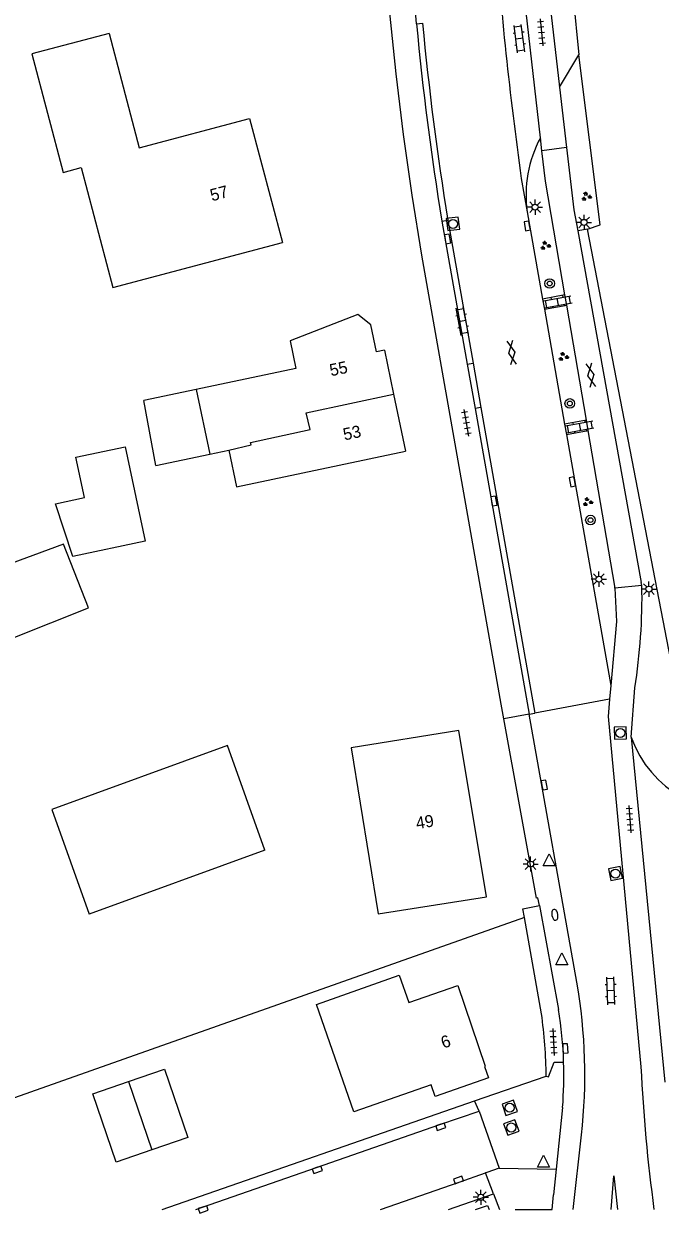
# Model space of a CAD drawing. Extents: x 136000 to 141000, y 400494 to 402006.
# Drawn here: x 137913.3 to 137966.1, y 400499.7 to 400598.3 of the extents above; entities that cross this region are included whole.
import ezdxf

# ---------------------------------------------------------------- set-up
doc = ezdxf.new("R2010")
doc.units = 0
for name, color, linetype in [('gg-afsc-erfafscheiding', 7, 'Continuous'), ('gg-afsc-hekwerk', 7, 'Continuous'), ('gg-anno-huisnummerreeks BGT', 7, 'Continuous'), ('gg-bbg-bijgebouw', 7, 'Continuous'), ('gg-bbg-gedigitaliseerde bebouwing', 7, 'Continuous'), ('gg-bbg-gedigitaliseerde bijgebouw', 7, 'Continuous'), ('gg-bbg-hoofdgebouw', 7, 'Continuous'), ('gg-bbg-tussenscheiding', 7, 'Continuous'), ('gg-knt-verharding', 7, 'Continuous'), ('gg-knt-verharding nz', 7, 'Continuous'), ('gt-grn-groengrens', 7, 'Continuous'), ('gt-grn-vlakafsluiter', 7, 'Continuous'), ('gt-grn-weggrens', 7, 'Continuous'), ('gt-symb-boom', 7, 'Continuous'), ('gt-symb-brandkraan', 7, 'Continuous'), ('gt-symb-gesloten verharding', 7, 'Continuous'), ('gt-symb-groenvak', 7, 'Continuous'), ('gt-symb-klinker verharding', 7, 'Continuous'), ('gt-symb-kolk', 7, 'Continuous'), ('gt-symb-lichtmast', 7, 'Continuous'), ('gt-symb-rioolschacht', 7, 'Continuous'), ('gt-symb-tegel verharding', 7, 'Continuous'), ('gt-symb-waterafsluiter', 7, 'Continuous')]:
    doc.layers.add(name, color=color, linetype=linetype)

# ---------------------------------------------------------------- blocks, each defined once
blk = doc.blocks.new('gt0-KL1')
at = {"layer": 'gt-symb-klinker verharding'}
for p, q in [((-1.15, 0.3), (1.15, 0.3)), ((-1, -0.3), (-1, 0.3)), ((-0.5, 0.3), (-0.5, 0.45)), ((0, -0.3), (0, 0.3)), ((0.5, 0.3), (0.5, 0.45)), ((1, -0.3), (1, 0.3)), ((-1.15, -0.3), (1.15, -0.3)), ((-0.5, -0.45), (-0.5, -0.3)), ((0.5, -0.45), (0.5, -0.3))]:
    blk.add_line(p, q, dxfattribs=at)
blk = doc.blocks.new('gt0-TEG1')
at = {"layer": 'gt-symb-tegel verharding'}
for p, q in [((-1.125, 0), (1.125, 0)), ((-0.9, -0.25), (-0.9, 0.25)), ((-0.45, -0.25), (-0.45, 0.25)), ((0, -0.25), (0, 0.25)), ((0.45, -0.25), (0.45, 0.25)), ((0.9, -0.25), (0.9, 0.25))]:
    blk.add_line(p, q, dxfattribs=at)
blk = doc.blocks.new('gt0-BOOM')
at = {"layer": 'gt-symb-boom'}
for radius in [0.4, 0.2]:
    blk.add_circle((0, 0), radius, dxfattribs=at)
blk = doc.blocks.new('gt0-GRVAK')
at = {"layer": 'gt-symb-groenvak'}
for p, q in [((-0.11, 0.189), (-0.228, 0.24)), ((-0.182, 0.153), (0.088, 0.153)), ((-0.091, 0.211), (-0.156, 0.322)), ((-0.047, 0.214), (-0.047, 0.393)), ((-0.004, 0.211), (0.061, 0.322)), ((0.015, 0.189), (0.133, 0.24)), ((0.262, -0.052), (0.197, 0.059)), ((0.305, -0.049), (0.305, 0.13)), ((0.349, -0.052), (0.414, 0.059)), ((-0.245, -0.228), (-0.363, -0.177)), ((-0.318, -0.264), (-0.047, -0.264)), ((-0.226, -0.206), (-0.291, -0.095)), ((-0.183, -0.203), (-0.183, -0.024)), ((-0.139, -0.206), (-0.074, -0.095)), ((-0.12, -0.228), (-0.002, -0.177)), ((0.243, -0.074), (0.125, -0.023)), ((0.17, -0.11), (0.441, -0.11)), ((0.368, -0.074), (0.486, -0.023))]:
    blk.add_line(p, q, dxfattribs=at)
blk = doc.blocks.new('gt0-KOLK')
at = {"layer": 'gt-symb-kolk'}
blk.add_lwpolyline([(0, 0), (0.375, 0), (0.375, 0.4), (-0.375, 0.4), (-0.375, 0), (0, 0)], dxfattribs=at)
blk = doc.blocks.new('gt0-LMAST')
at = {"layer": 'gt-symb-lichtmast'}
for p, q in [((-0.182, 0.173), (-0.447, 0.438)), ((-0.005, 0.246), (-0.005, 0.621)), ((0.172, 0.173), (0.437, 0.438)), ((-0.255, -0.004), (-0.63, -0.004)), ((-0.182, -0.181), (-0.447, -0.446)), ((-0.005, -0.254), (-0.005, -0.629)), ((0.437, -0.446), (0.172, -0.181)), ((0.245, -0.004), (0.62, -0.004))]:
    blk.add_line(p, q, dxfattribs=at)
blk.add_circle((-0.005, -0.004), 0.25, dxfattribs=at)
blk = doc.blocks.new('gt0-GESVH1')
at = {"layer": 'gt-symb-gesloten verharding'}
for p, q in [((-0.992, -0.261), (0.008, 0.239)), ((0.008, -0.261), (-0.992, 0.239)), ((0.008, 0.239), (1.008, -0.261)), ((1.008, 0.239), (0.008, -0.261))]:
    blk.add_line(p, q, dxfattribs=at)
blk = doc.blocks.new('gt0-RS')
at = {"layer": 'gt-symb-rioolschacht'}
blk.add_lwpolyline([(-0.5, -0.5), (0.5, -0.5), (0.5, 0.5), (-0.5, 0.5)], close=True, dxfattribs=at)
blk.add_circle((0, 0), 0.375, dxfattribs=at)
blk = doc.blocks.new('gt0-WAFSL')
at = {"layer": 'gt-symb-waterafsluiter'}
for p, q in [((-0.5, -0.333), (0, 0.667)), ((0, 0.667), (0.5, -0.333)), ((0.5, -0.333), (-0.5, -0.333))]:
    blk.add_line(p, q, dxfattribs=at)
blk = doc.blocks.new('gt0-BR')
at = {"layer": 'gt-symb-brandkraan'}
for centre, radius, start, end in [((-0.244, 0), 0.206, 107.56694, 252.43307), ((0.599, -2.664), 3, 106.89205, 107.56694), ((0, -0.691), 0.938, 73.10799, 106.89205), ((-0.599, -2.664), 3, 72.43309, 73.10799), ((0.244, 0), 0.206, 287.56695, 72.43309), ((0.599, 2.664), 3, 252.43307, 253.10797), ((0, 0.691), 0.938, 253.10797, 286.89206), ((-0.599, 2.664), 3, 286.89206, 287.56695)]:
    blk.add_arc(centre, radius, start, end, dxfattribs=at)

msp = doc.modelspace()

# ---------------------------------------------------------------- linework, layer by layer
at = {"layer": 'gg-afsc-erfafscheiding'}
for p, q in [((137958.199, 400607.146), (137959.332, 400595.725)), ((137954.822, 400524.219), (137888.451, 400500.743))]:
    msp.add_line(p, q, dxfattribs=at)
at = {"layer": 'gg-afsc-hekwerk'}
for points in [[(137960.064, 400581.277), (137961.101, 400581.627), (137959.332, 400595.725)], [(137984.525, 400540.311), (137968.565, 400537.24), (137960.064, 400581.277)]]:
    msp.add_lwpolyline(points, dxfattribs=at)
at = {"layer": 'gg-bbg-bijgebouw'}
for p, q in [((137933.305, 400529.801), (137918.721, 400524.489)), ((137926.909, 400505.977), (137923.936, 400504.955))]:
    msp.add_line(p, q, dxfattribs=at)
for points in [[(137921.993, 400510.61), (137924.964, 400511.632), (137926.909, 400505.977)], [(137923.936, 400504.955), (137920.963, 400503.932), (137919.021, 400509.588), (137921.993, 400510.61)]]:
    msp.add_lwpolyline(points, dxfattribs=at)
at = {"layer": 'gg-bbg-gedigitaliseerde bebouwing'}
for p, q in [((137935.877, 400569.71), (137927.592, 400567.982)), ((137928.743, 400562.62), (137930.311, 400562.949))]:
    msp.add_line(p, q, dxfattribs=at)
for points in [[(137920.39, 400597.49), (137913.978, 400595.804), (137916.562, 400585.978), (137918.069, 400586.385), (137920.705, 400576.438), (137934.75, 400580.16)], [(137930.311, 400562.949), (137930.95, 400559.907), (137944.97, 400562.86)], [(137949.4, 400539.7), (137940.445, 400538.265), (137942.698, 400524.518)]]:
    msp.add_lwpolyline(points, dxfattribs=at)
at = {"layer": 'gg-bbg-gedigitaliseerde bijgebouw'}
for p, q in [((137927.592, 400567.982), (137923.256, 400567.078)), ((137924.27, 400561.68), (137923.256, 400567.078)), ((137924.27, 400561.68), (137928.743, 400562.62))]:
    msp.add_line(p, q, dxfattribs=at)
for points in [[(137915.93, 400558.516), (137918.328, 400559.019), (137917.626, 400562.365), (137921.722, 400563.226), (137923.365, 400555.396), (137917.375, 400554.139), (137915.93, 400558.516)], [(137916.593, 400555.172), (137904.065, 400550.556), (137906.279, 400544.971), (137918.684, 400549.89), (137916.593, 400555.172)], [(137933.305, 400529.801), (137930.213, 400538.475), (137915.637, 400533.157), (137918.721, 400524.489)]]:
    msp.add_lwpolyline(points, dxfattribs=at)
at = {"layer": 'gg-bbg-hoofdgebouw'}
for p, q in [((137943.21, 400571.24), (137943.977, 400567.588)), ((137943.977, 400567.588), (137944.97, 400562.86))]:
    msp.add_line(p, q, dxfattribs=at)
for points in [[(137920.39, 400597.49), (137922.88, 400588.02), (137932.04, 400590.44), (137934.75, 400580.16)], [(137943.21, 400571.24), (137942.564, 400571.104), (137942.094, 400573.335), (137941.001, 400574.193), (137935.39, 400572.03), (137935.877, 400569.71)], [(137942.698, 400524.518), (137951.684, 400525.917), (137949.4, 400539.7)], [(137937.573, 400517.01), (137944.444, 400519.425), (137945.236, 400517.151), (137949.299, 400518.564), (137951.585, 400511.889), (137951.518, 400511.866), (137951.845, 400510.929), (137947.413, 400509.383), (137947.083, 400510.33), (137940.678, 400508.109), (137937.573, 400517.01)]]:
    msp.add_lwpolyline(points, dxfattribs=at)
at = {"layer": 'gg-bbg-tussenscheiding'}
for p, q in [((137927.592, 400567.982), (137928.743, 400562.62)), ((137921.993, 400510.61), (137923.936, 400504.955))]:
    msp.add_line(p, q, dxfattribs=at)
msp.add_lwpolyline([(137930.311, 400562.949), (137932.157, 400563.384), (137932.107, 400563.596), (137937.07, 400564.658), (137936.716, 400566.044), (137943.977, 400567.588)], dxfattribs=at)
at = {"layer": 'gg-knt-verharding'}
for p, q in [((137956.156, 400588.857), (137954.361, 400604.552)), ((137956.378, 400604.724), (137957.743, 400593.041)), ((137945.883, 400598.3), (137946.378, 400598.347)), ((137957.743, 400593.041), (137959.332, 400595.725)), ((137957.743, 400593.041), (137958.328, 400588.044)), ((137956.283, 400587.754), (137956.156, 400588.857)), ((137958.328, 400588.044), (137956.283, 400587.754)), ((137954.57, 400585.48), (137955.058, 400582.716)), ((137955.058, 400582.716), (137956.338, 400575.459)), ((137947.98, 400581.95), (137948.481, 400582.032)), ((137947.98, 400581.95), (137950.081, 400570.086)), ((137948.481, 400582.032), (137950.571, 400570.172)), ((137959.248, 400581.13), (137964.51, 400551.991)), ((137958.188, 400575.827), (137956.338, 400575.459)), ((137956.338, 400575.459), (137956.484, 400574.634)), ((137958.335, 400574.976), (137958.188, 400575.827)), ((137956.484, 400574.634), (137958.335, 400574.976)), ((137956.484, 400574.634), (137958.164, 400565.114)), ((137959.975, 400565.438), (137958.335, 400574.976)), ((137950.081, 400570.086), (137950.571, 400570.172)), ((137950.081, 400570.086), (137950.735, 400566.397)), ((137950.571, 400570.172), (137951.221, 400566.483)), ((137951.221, 400566.483), (137950.735, 400566.397)), ((137950.735, 400566.397), (137955.222, 400541.057)), ((137951.221, 400566.483), (137955.686, 400541.14)), ((137959.975, 400565.438), (137958.164, 400565.114)), ((137960.123, 400564.577), (137959.975, 400565.438)), ((137958.164, 400565.114), (137958.318, 400564.238)), ((137958.318, 400564.238), (137960.123, 400564.577)), ((137962.34, 400551.681), (137960.123, 400564.577)), ((137958.318, 400564.238), (137961.986, 400543.452)), ((137964.573, 400551.737), (137962.329, 400551.502)), ((137962.329, 400551.502), (137962.34, 400551.681)), ((137964.573, 400551.737), (137964.51, 400551.991)), ((137961.986, 400543.452), (137961.882, 400542.299)), ((137963.691, 400539.166), (137963.992, 400543.248)), ((137961.882, 400542.299), (137955.686, 400541.14)), ((137959.176, 400518.838), (137955.222, 400541.057)), ((137963.691, 400539.166), (137966.466, 400510.567)), ((137954.697, 400524.92), (137956.078, 400525.216)), ((137956.078, 400525.216), (137957.667, 400516.57)), ((137954.822, 400524.219), (137954.697, 400524.92)), ((137956.248, 400516.232), (137954.822, 400524.219)), ((137950.698, 400509), (137956.635, 400511.047)), ((137924.796, 400500), (137950.698, 400509)), ((137957.995, 400508.445), (137957.466, 400503.359)), ((137951.068, 400508.154), (137952.722, 400503.44)), ((137958.879, 400500), (137959.564, 400506.18)), ((137952.722, 400503.44), (137951.719, 400503.076)), ((137952.722, 400503.44), (137957.466, 400503.359)), ((137957.466, 400503.359), (137957.243, 400501.216)), ((137951.719, 400503.076), (137951.611, 400503.038)), ((137952.275, 400501.298), (137951.611, 400503.038)), ((137948.543, 400500), (137952.275, 400501.298)), ((137952.275, 400501.298), (137952.77, 400500)), ((137957.12, 400500.002), (137957.243, 400501.216)), ((137954.058, 400500), (137956.758, 400500.003)), ((137956.756, 400500), (137956.758, 400500.003)), ((137956.758, 400500.003), (137957.12, 400500.002)), ((137957.12, 400500), (137957.12, 400500.002))]:
    msp.add_line(p, q, dxfattribs=at)
for points in [[(137953.118, 400540.684), (137952.895, 400541.907), (137946.331, 400579.107), (137945.505, 400584.105), (137944.787, 400589.12), (137944.179, 400594.152), (137943.676, 400599.195), (137943.255, 400604.384), (137942.945, 400609.581), (137942.751, 400615.175), (137942.658, 400620.772), (137942.643, 400626.229), (137942.694, 400631.685), (137942.719, 400632.779)], [(137945.883, 400598.3), (137945.41, 400604.025), (137945.058, 400609.735), (137945.056, 400609.785)], [(137958.188, 400575.827), (137956.57, 400585.24), (137956.283, 400587.754)], [(137958.328, 400588.044), (137958.93, 400582.89), (137959.248, 400581.13)], [(137962.329, 400551.502), (137962.465, 400548.748), (137961.986, 400543.452)], [(137961.882, 400542.299), (137961.784, 400540.883), (137964.496, 400511.834)], [(137956.078, 400525.216), (137955.952, 400525.84), (137955.834, 400525.811), (137953.118, 400540.684)], [(137956.635, 400511.047), (137956.816, 400511.001), (137957.285, 400512.223), (137958.083, 400512.206)], [(137927.565, 400500), (137928.124, 400500.195), (137937.589, 400503.478), (137947.826, 400507.048), (137951.068, 400508.154)], [(137942.897, 400500), (137949.427, 400502.265), (137951.611, 400503.038)]]:
    msp.add_lwpolyline(points, dxfattribs=at)
for centre, radius, start, end in [((138246.395, 400626.641), 294.714, 183.96826, 188.02849), ((138179.597, 400619.966), 234.716, 185.29635, 189.32101), ((138188.724, 400621.292), 243.43, 185.40864, 189.28119), ((137965.085, 400584.092), 10.121, 151.91214, 187.81333), ((137915.284, 400550.846), 49.297, 351.13382, 1.03557), ((137972.309, 400542.169), 9.126, 199.21396, 282.82777), ((137915.286, 400511.158), 44.556, 353.58569, 9.92574), ((137914.114, 400510.48), 42.525, 0.76363, 7.77347), ((137923.779, 400511.138), 34.321, 1.78362, 9.10696), ((137924.036, 400511.121), 34.064, 355.49417, 1.8251), ((138100.648, 400518.27), 136.304, 182.70659, 187.70322)]:
    msp.add_arc(centre, radius, start, end, dxfattribs=at)
at = {"layer": 'gg-knt-verharding nz'}
msp.add_lwpolyline([(137962.022, 400500), (137962.243, 400502.797), (137962.536, 400500)], dxfattribs=at)
at = {"layer": 'gt-grn-groengrens'}
for p, q in [((137960.064, 400581.277), (137959.248, 400581.13)), ((137950.763, 400500), (137951.78, 400500.347)), ((137951.78, 400500.347), (137951.898, 400500))]:
    msp.add_line(p, q, dxfattribs=at)
at = {"layer": 'gt-grn-vlakafsluiter'}
for p, q in [((137955.222, 400541.057), (137955.686, 400541.14)), ((137951.068, 400508.154), (137950.698, 400509))]:
    msp.add_line(p, q, dxfattribs=at)
at = {"layer": 'gt-grn-weggrens'}
msp.add_line((137955.222, 400541.057), (137953.118, 400540.684), dxfattribs=at)

# ---------------------------------------------------------------- block references
at = {"layer": 'gt-symb-boom'}
for p in [(137956.922, 400576.769), (137958.593, 400566.823), (137960.307, 400557.155)]:
    msp.add_blockref('gt0-BOOM', p, dxfattribs=at)
at = {"layer": 'gt-symb-brandkraan', "rotation": 100.25359802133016}
msp.add_blockref('gt0-BR', (137957.355, 400524.426), dxfattribs=at)
at = {"layer": 'gt-symb-gesloten verharding'}
for p, rotation in [((137953.764, 400571.033), 98.9726266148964), ((137960.351, 400569.18), -80.09492079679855)]:
    msp.add_blockref('gt0-GESVH1', p, dxfattribs=dict(at, rotation=rotation))
at = {"layer": 'gt-symb-groenvak'}
for p in [(137959.963, 400583.979), (137956.564, 400579.911), (137958.057, 400570.696), (137960.068, 400558.663)]:
    msp.add_blockref('gt0-GRVAK', p, dxfattribs=at)
at = {"layer": 'gt-symb-klinker verharding'}
for p, rotation in [((137954.415, 400597.065), 97.18187853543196), ((137957.611, 400575.256), 10.309970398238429), ((137949.668, 400573.641), 100.71464389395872), ((137959.414, 400564.856), -169.74640197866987), ((137961.993, 400518.135), 92.00653893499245)]:
    msp.add_blockref('gt0-KL1', p, dxfattribs=dict(at, rotation=rotation))
at = {"layer": 'gt-symb-kolk'}
for p, rotation in [((137955.257, 400581.574), 100.07433273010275), ((137948.255, 400580.427), -79.98206552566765), ((137959, 400560.364), 100.07433273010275), ((137952.097, 400558.704), -80.03848340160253), ((137956.28, 400535.16), -79.92566726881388), ((137958.028, 400513.348), -86.33074590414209), ((137947.826, 400507.048), -160.80707292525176), ((137937.589, 400503.478), -160.80707292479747), ((137949.427, 400502.265), 19.23368461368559), ((137928.124, 400500.195), -160.80707292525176)]:
    msp.add_blockref('gt0-KOLK', p, dxfattribs=dict(at, rotation=rotation))
at = {"layer": 'gt-symb-lichtmast'}
for p in [(137955.719, 400583.104), (137959.784, 400581.838), (137961.007, 400552.261), (137965.159, 400551.436), (137955.344, 400528.639), (137951.218, 400501.017)]:
    msp.add_blockref('gt0-LMAST', p, dxfattribs=at)
at = {"layer": 'gt-symb-rioolschacht'}
for p, rotation in [((137948.903, 400581.713), -83.05258934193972), ((137962.778, 400539.512), -88.1653270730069), ((137962.381, 400527.851), 11.186329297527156), ((137953.606, 400508.433), 18.866196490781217), ((137953.738, 400506.798), 20.392645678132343)]:
    msp.add_blockref('gt0-RS', p, dxfattribs=dict(at, rotation=rotation))
at = {"layer": 'gt-symb-tegel verharding'}
for p, rotation in [((137956.242, 400597.593), -84.43197594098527), ((137950.017, 400565.21), 100.14079314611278), ((137963.58, 400532.362), -85.92663550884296), ((137957.24, 400513.894), -87.19194693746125)]:
    msp.add_blockref('gt0-TEG1', p, dxfattribs=dict(at, rotation=rotation))
at = {"layer": 'gt-symb-waterafsluiter'}
for p in [(137956.885, 400528.819), (137957.921, 400520.613), (137956.416, 400503.841)]:
    msp.add_blockref('gt0-WAFSL', p, dxfattribs=at)

# ---------------------------------------------------------------- texts
at = {"layer": 'gg-anno-huisnummerreeks BGT'}
for s, rotation, p in [('57', 14.8, (137928.909, 400583.578)), ('55', 11.9, (137938.784, 400569.074)), ('53', 11.9, (137939.902, 400563.754)), ('49', 9.4, (137945.911, 400531.528)), ('6', 19.2, (137948.11, 400513.333))]:
    msp.add_text(s, height=1, rotation=rotation, dxfattribs=at).set_placement(p)

doc.saveas('drawing.dxf')
